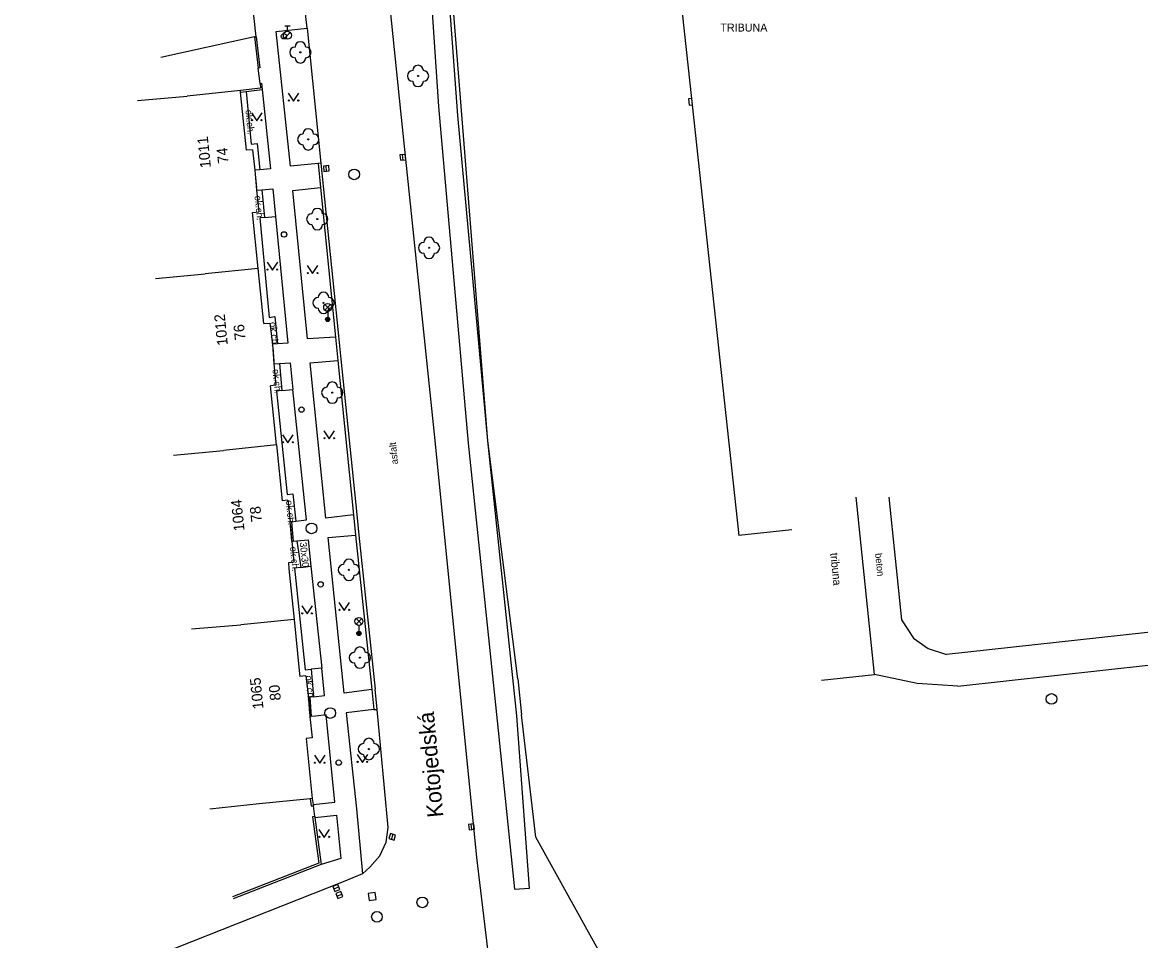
# Model space of a CAD drawing. Extents: x -539694 to -539148, y -1156467 to -1155920.
# Drawn here: x -539664.8 to -539560, y -1156272.3 to -1156186.2 of the extents above; entities that cross this region are included whole.
import ezdxf

# ---------------------------------------------------------------- set-up
doc = ezdxf.new("R2010")
doc.units = 0
for name, color, linetype in [('Vrstva 10', 7, 'Continuous'), ('Vrstva 11', 7, 'Continuous'), ('Vrstva 22', 7, 'Continuous'), ('Vrstva 24', 7, 'Continuous'), ('Vrstva 27', 7, 'Continuous'), ('Vrstva 28', 7, 'Continuous'), ('Vrstva 33', 7, 'Continuous'), ('Vrstva 36', 7, 'Continuous'), ('Vrstva 40', 7, 'Continuous'), ('Vrstva 41', 7, 'Continuous'), ('Vrstva 46', 7, 'Continuous'), ('Vrstva 47', 7, 'Continuous'), ('Vrstva 49', 7, 'Continuous'), ('Vrstva 5', 7, 'Continuous'), ('Vrstva 6', 7, 'Continuous'), ('Vrstva 7', 7, 'Continuous'), ('Vrstva 8', 7, 'Continuous')]:
    doc.layers.add(name, color=color, linetype=linetype)

msp = doc.modelspace()

# ---------------------------------------------------------------- linework, layer by layer
at = {"layer": 'Vrstva 10'}
for p, q in [((-539629.3, -1156194.54), (-539635.12, -1156137.96)), ((-539626.09, -1156225.38), (-539629.3, -1156194.54)), ((-539622.17, -1156264.46), (-539626.09, -1156225.38)), ((-539633.24, -1156234.25), (-539631.72, -1156248.69)), ((-539620.83, -1156275.84), (-539622.17, -1156264.46))]:
    msp.add_line(p, q, dxfattribs=at)
for points in [[(-539630.48, -1156261.66), (-539631.537, -1156250.605), (-539631.72, -1156248.69)], [(-539632.28, -1156268.5), (-539631.61, -1156268.41), (-539631.7, -1156267.74), (-539632.37, -1156267.83), (-539632.28, -1156268.5)]]:
    msp.add_lwpolyline(points, dxfattribs=at)
at = {"layer": 'Vrstva 11'}
for p, q in [((-539627.3, -1156171.99), (-539625.77, -1156194.09)), ((-539623.95, -1156194.94), (-539625.639, -1156171.992)), ((-539640.98, -1156187.07), (-539638.09, -1156186.77)), ((-539638.09, -1156186.77), (-539636.805, -1156199.4)), ((-539639.64, -1156199.69), (-539640.98, -1156187.07)), ((-539642.302, -1156192.518), (-539641.52, -1156199.93)), ((-539625.77, -1156194.09), (-539623.01, -1156225.65)), ((-539636.805, -1156199.4), (-539636.583, -1156201.569)), ((-539637.05, -1156199.44), (-539639.64, -1156199.69)), ((-539639.44, -1156201.98), (-539636.84, -1156201.68)), ((-539638.04, -1156215.87), (-539639.44, -1156201.98)), ((-539636.84, -1156201.68), (-539635.42, -1156215.7)), ((-539636.583, -1156201.569), (-539635.148, -1156215.599)), ((-539642.09, -1156204.5), (-539642.53, -1156204.53)), ((-539642.53, -1156204.53), (-539641.63, -1156213.88)), ((-539641.05, -1156204.42), (-539639.88, -1156216.28)), ((-539635.42, -1156215.7), (-539638.04, -1156215.87)), ((-539635.42, -1156215.7), (-539635.2, -1156217.9)), ((-539635.148, -1156215.599), (-539634.925, -1156217.779)), ((-539637.79, -1156218.13), (-539635.2, -1156217.9)), ((-539636.33, -1156232.68), (-539637.79, -1156218.13)), ((-539635.2, -1156217.9), (-539633.74, -1156232.36)), ((-539634.925, -1156217.779), (-539633.436, -1156232.335)), ((-539640.46, -1156220.71), (-539640.96, -1156220.76)), ((-539640.96, -1156220.76), (-539639.95, -1156230.45)), ((-539638.16, -1156232.83), (-539639.41, -1156220.62)), ((-539623.01, -1156225.65), (-539620.28, -1156251.66)), ((-539584.92, -1156247.33), (-539586.63, -1156230.7)), ((-539583.57, -1156230.69), (-539582.38, -1156242.19)), ((-539633.74, -1156232.36), (-539636.33, -1156232.68)), ((-539633.74, -1156232.36), (-539633.54, -1156234.26)), ((-539633.436, -1156232.335), (-539633.24, -1156234.25)), ((-539639.55, -1156233.02), (-539639.68, -1156233.03)), ((-539639.55, -1156233.02), (-539639.39, -1156234.83)), ((-539639.53, -1156234.84), (-539639.39, -1156234.83)), ((-539636.12, -1156234.49), (-539633.54, -1156234.26)), ((-539634.63, -1156249.08), (-539636.12, -1156234.49)), ((-539633.54, -1156234.26), (-539632.03, -1156248.74)), ((-539638.69, -1156237.28), (-539639.27, -1156237.35)), ((-539639.27, -1156237.35), (-539638.27, -1156246.89)), ((-539637.74, -1156237.16), (-539636.72, -1156246.74)), ((-539509.19, -1156237.87), (-539578.17, -1156245.46)), ((-539582.38, -1156242.19), (-539581.25, -1156243.9)), ((-539581.25, -1156243.9), (-539579.89, -1156244.87)), ((-539579.89, -1156244.87), (-539578.17, -1156245.46)), ((-539577.12, -1156248.42), (-539558.98, -1156246.41)), ((-539638.27, -1156246.89), (-539637.72, -1156246.83)), ((-539589.894, -1156247.841), (-539584.92, -1156247.33)), ((-539580.92, -1156248.17), (-539584.92, -1156247.33)), ((-539577.12, -1156248.42), (-539580.92, -1156248.17)), ((-539637.97, -1156249.46), (-539637.84, -1156249.45)), ((-539637.84, -1156249.45), (-539637.7, -1156251.26)), ((-539632.03, -1156248.74), (-539634.63, -1156249.08)), ((-539631.85, -1156250.61), (-539634.42, -1156250.91)), ((-539637.83, -1156251.27), (-539637.7, -1156251.26)), ((-539635.49, -1156259.29), (-539636.29, -1156251.11)), ((-539634.42, -1156250.91), (-539633.47, -1156259.91)), ((-539620.28, -1156251.66), (-539618.65, -1156267.42)), ((-539617.26, -1156267.35), (-539618.45, -1156251.19)), ((-539637.515, -1156259.509), (-539635.49, -1156259.29)), ((-539633.47, -1156259.91), (-539632.9, -1156266.01)), ((-539632.9, -1156266.01), (-539634.71, -1156266.76)), ((-539634.71, -1156266.76), (-539664.77, -1156278.6)), ((-539618.65, -1156267.42), (-539617.26, -1156267.35))]:
    msp.add_line(p, q, dxfattribs=at)
for points in [[(-539638.09, -1156186.77), (-539638.34, -1156184.59), (-539638.35, -1156184.32)], [(-539643.783, -1156192.694), (-539643.32, -1156197.64), (-539642.77, -1156197.57), (-539642.53, -1156200.02)], [(-539618.45, -1156251.19), (-539621.153, -1156225.416), (-539623.95, -1156194.94)], [(-539636.805, -1156199.4), (-539637.05, -1156199.44), (-539636.84, -1156201.68)], [(-539641.52, -1156199.93), (-539642.53, -1156200.02), (-539643, -1156200.06)], [(-539642.82, -1156201.95), (-539642.34, -1156201.91), (-539642.09, -1156204.5), (-539641.05, -1156204.42)], [(-539642.34, -1156201.91), (-539641.31, -1156201.83), (-539641.05, -1156204.42)], [(-539641.63, -1156213.88), (-539641.1, -1156213.79), (-539640.86, -1156216.34)], [(-539639.88, -1156216.28), (-539640.86, -1156216.34), (-539641.33, -1156216.37)], [(-539641.19, -1156218.22), (-539640.68, -1156218.19), (-539640.46, -1156220.71), (-539639.41, -1156220.62)], [(-539640.68, -1156218.19), (-539639.67, -1156218.12), (-539639.41, -1156220.62)], [(-539639.95, -1156230.45), (-539639.41, -1156230.39), (-539639.15, -1156232.96)], [(-539639.55, -1156233.02), (-539639.15, -1156232.96), (-539638.16, -1156232.83)], [(-539639.39, -1156234.83), (-539639.04, -1156234.79), (-539638.69, -1156237.28), (-539637.74, -1156237.16)], [(-539639.04, -1156234.79), (-539637.99, -1156234.69), (-539637.74, -1156237.16)], [(-539636.72, -1156246.74), (-539637.72, -1156246.83), (-539637.48, -1156249.41), (-539637.84, -1156249.45)], [(-539637.48, -1156249.41), (-539636.46, -1156249.3), (-539636.72, -1156246.74)], [(-539632.03, -1156248.74), (-539631.85, -1156250.61), (-539631.537, -1156250.605)], [(-539636.29, -1156251.11), (-539637.28, -1156251.21), (-539637.7, -1156251.26)], [(-539637.357, -1156260.714), (-539635.34, -1156260.5), (-539634.93, -1156264.57), (-539636.77, -1156265.12)], [(-539632.9, -1156266.01), (-539632.199, -1156265.356), (-539631.277, -1156264.308), (-539630.688, -1156263.041), (-539630.48, -1156261.66)]]:
    msp.add_lwpolyline(points, dxfattribs=at)
at = {"layer": 'Vrstva 22'}
for centre in [(-539638.72, -1156189.03), (-539627.69, -1156191.24), (-539637.98, -1156197.18), (-539637.13, -1156204.65), (-539626.66, -1156207.34), (-539636.55, -1156212.5), (-539635.73, -1156220.91), (-539634.17, -1156237.51), (-539633.14, -1156245.74), (-539632.3, -1156254.3)]:
    msp.add_circle(centre, 0.05, dxfattribs=at)
for centre, start, end in [((-539639.22, -1156189.03), 90, 270), ((-539638.72, -1156188.53), 0, 180), ((-539638.22, -1156189.03), 270, 90), ((-539638.72, -1156189.53), 180, 0), ((-539628.19, -1156191.24), 90, 270), ((-539627.69, -1156190.74), 0, 180), ((-539627.19, -1156191.24), 270, 90), ((-539627.69, -1156191.74), 180, 0), ((-539637.98, -1156196.68), 0, 180), ((-539638.48, -1156197.18), 90, 270), ((-539637.48, -1156197.18), 270, 90), ((-539637.98, -1156197.68), 180, 0), ((-539637.63, -1156204.65), 90, 270), ((-539637.13, -1156204.15), 0, 180), ((-539636.63, -1156204.65), 270, 90), ((-539637.13, -1156205.15), 180, 0), ((-539626.66, -1156206.84), 0, 180), ((-539627.16, -1156207.34), 90, 270), ((-539626.16, -1156207.34), 270, 90), ((-539626.66, -1156207.84), 180, 0), ((-539636.55, -1156212), 0, 180), ((-539637.05, -1156212.5), 90, 270), ((-539636.55, -1156213), 180, 0), ((-539636.05, -1156212.5), 270, 90), ((-539635.73, -1156220.41), 0, 180), ((-539636.23, -1156220.91), 90, 270), ((-539635.73, -1156221.41), 180, 0), ((-539635.23, -1156220.91), 270, 90), ((-539634.67, -1156237.51), 90, 270), ((-539634.17, -1156237.01), 0, 180), ((-539633.67, -1156237.51), 270, 90), ((-539634.17, -1156238.01), 180, 0), ((-539633.64, -1156245.74), 90, 270), ((-539633.14, -1156245.24), 0, 180), ((-539632.64, -1156245.74), 270, 90), ((-539633.14, -1156246.24), 180, 0), ((-539632.8, -1156254.3), 90, 270), ((-539632.3, -1156253.8), 0, 180), ((-539631.8, -1156254.3), 270, 90), ((-539632.3, -1156254.8), 180, 0)]:
    msp.add_arc(centre, 0.5, start, end, dxfattribs=at)
at = {"layer": 'Vrstva 24'}
msp.add_lwpolyline([(-539602.059, -1156193.342), (-539602.357, -1156193.374), (-539602.293, -1156193.97), (-539601.994, -1156193.938)], dxfattribs=at)
at = {"layer": 'Vrstva 27'}
for p, q in [((-539629.096, -1156199.119), (-539629.144, -1156198.621)), ((-539636.266, -1156200.159), (-539636.314, -1156199.661)), ((-539630.184, -1156262.769), (-539630.036, -1156262.291)), ((-539622.656, -1156261.839), (-539622.704, -1156261.341)), ((-539635.592, -1156267.414), (-539635.128, -1156267.226)), ((-539635.292, -1156268.074), (-539634.828, -1156267.886))]:
    msp.add_line(p, q, dxfattribs=at)
for points in [[(-539628.847, -1156199.095), (-539628.895, -1156198.597), (-539629.393, -1156198.645), (-539629.345, -1156199.143)], [(-539636.017, -1156200.135), (-539636.065, -1156199.637), (-539636.563, -1156199.685), (-539636.515, -1156200.183)], [(-539629.945, -1156262.843), (-539629.797, -1156262.365), (-539630.275, -1156262.217), (-539630.423, -1156262.695)], [(-539622.407, -1156261.814), (-539622.456, -1156261.317), (-539622.953, -1156261.366), (-539622.904, -1156261.863)], [(-539635.498, -1156267.646), (-539635.034, -1156267.458), (-539635.222, -1156266.994), (-539635.686, -1156267.182)], [(-539635.198, -1156268.306), (-539634.734, -1156268.118), (-539634.922, -1156267.654), (-539635.386, -1156267.842)]]:
    msp.add_lwpolyline(points, close=True, dxfattribs=at)
for centre in [(-539633.68, -1156200.46), (-539637.67, -1156233.63), (-539568.33, -1156249.61), (-539635.92, -1156250.93), (-539627.29, -1156268.67), (-539631.54, -1156270.02)]:
    msp.add_circle(centre, 0.5, dxfattribs=at)
at = {"layer": 'Vrstva 28'}
for p, q in [((-539640.19, -1156186.554), (-539639.69, -1156186.554)), ((-539639.94, -1156187.054), (-539639.94, -1156186.554)), ((-539640.199, -1156187.701), (-539639.669, -1156187.171))]:
    msp.add_line(p, q, dxfattribs=at)
for centre, radius in [((-539640.26, -1156187.52), 0.25), ((-539639.94, -1156187.43), 0.375), ((-539640.25, -1156206.09), 0.25), ((-539638.61, -1156222.5), 0.25), ((-539636.82, -1156238.88), 0.25), ((-539635.13, -1156255.57), 0.25)]:
    msp.add_circle(centre, radius, dxfattribs=at)
at = {"layer": 'Vrstva 33'}
for p, q in [((-539636.425, -1156213.19), (-539635.895, -1156212.66)), ((-539636.425, -1156212.66), (-539635.895, -1156213.19)), ((-539636.16, -1156213.3), (-539636.16, -1156214.05)), ((-539633.495, -1156242.61), (-539632.965, -1156242.08)), ((-539633.495, -1156242.08), (-539632.965, -1156242.61)), ((-539633.23, -1156242.72), (-539633.23, -1156243.47))]:
    msp.add_line(p, q, dxfattribs=at)
for centre, radius in [((-539636.16, -1156212.925), 0.375), ((-539636.16, -1156214.05), 0.2), ((-539636.16, -1156214.05), 0.145), ((-539636.16, -1156214.05), 0.0876), ((-539633.23, -1156242.345), 0.375), ((-539633.23, -1156243.47), 0.2), ((-539633.23, -1156243.47), 0.145), ((-539633.23, -1156243.47), 0.0876)]:
    msp.add_circle(centre, radius, dxfattribs=at)
at = {"layer": 'Vrstva 36'}
for points in [[(-539639.86, -1156192.84), (-539639.36, -1156193.59), (-539638.86, -1156192.84)], [(-539643.3, -1156194.68), (-539642.8, -1156195.43), (-539642.3, -1156194.68)], [(-539641.84, -1156208.68), (-539641.34, -1156209.43), (-539640.84, -1156208.68)], [(-539638.07, -1156209.01), (-539637.57, -1156209.76), (-539637.07, -1156209.01)], [(-539636.51, -1156224.48), (-539636.01, -1156225.23), (-539635.51, -1156224.48)], [(-539640.38, -1156224.86), (-539639.88, -1156225.61), (-539639.38, -1156224.86)], [(-539638.59, -1156240.89), (-539638.09, -1156241.64), (-539637.59, -1156240.89)], [(-539635.1, -1156240.56), (-539634.6, -1156241.31), (-539634.1, -1156240.56)], [(-539637.41, -1156254.89), (-539636.91, -1156255.64), (-539636.41, -1156254.89)], [(-539633.4, -1156254.8), (-539632.9, -1156255.55), (-539632.4, -1156254.8)], [(-539636.98, -1156261.83), (-539636.48, -1156262.58), (-539635.98, -1156261.83)]]:
    msp.add_lwpolyline(points, dxfattribs=at)
for centre in [(-539639.81, -1156193.54), (-539638.911, -1156193.54), (-539643.25, -1156195.38), (-539642.351, -1156195.38), (-539641.79, -1156209.38), (-539640.891, -1156209.38), (-539638.02, -1156209.71), (-539637.121, -1156209.71), (-539640.33, -1156225.56), (-539639.431, -1156225.56), (-539636.46, -1156225.18), (-539635.561, -1156225.18), (-539635.05, -1156241.26), (-539634.151, -1156241.26), (-539638.54, -1156241.59), (-539637.641, -1156241.59), (-539637.36, -1156255.59), (-539636.461, -1156255.59), (-539633.35, -1156255.5), (-539632.451, -1156255.5), (-539636.93, -1156262.53), (-539636.031, -1156262.53)]:
    msp.add_circle(centre, 0.05, dxfattribs=at)
at = {"layer": 'Vrstva 5'}
for p, q in [((-539606.99, -1156147.74), (-539602.059, -1156193.342)), ((-539653.986, -1156193.541), (-539649.314, -1156193.118)), ((-539644.34, -1156192.61), (-539649.314, -1156193.118)), ((-539602.059, -1156193.342), (-539601.994, -1156193.938)), ((-539601.994, -1156193.938), (-539597.63, -1156234.3)), ((-539643.21, -1156198.15), (-539643.775, -1156198.207)), ((-539643.21, -1156198.15), (-539643, -1156200.06)), ((-539643, -1156200.06), (-539642.82, -1156201.95)), ((-539642.82, -1156201.95), (-539642.61, -1156203.96)), ((-539643.19, -1156204.018), (-539642.61, -1156203.96)), ((-539642.66, -1156209.27), (-539643.19, -1156204.018)), ((-539652.3, -1156210.212), (-539647.634, -1156209.778)), ((-539642.66, -1156209.27), (-539647.634, -1156209.778)), ((-539642.128, -1156214.446), (-539642.66, -1156209.27)), ((-539642.128, -1156214.446), (-539641.58, -1156214.39)), ((-539641.58, -1156214.39), (-539641.33, -1156216.37)), ((-539641.33, -1156216.37), (-539641.19, -1156218.22)), ((-539641.19, -1156218.22), (-539641.01, -1156220.21)), ((-539641.01, -1156220.21), (-539641.53, -1156220.263)), ((-539640.96, -1156225.81), (-539641.53, -1156220.263)), ((-539650.597, -1156226.779), (-539645.934, -1156226.318)), ((-539640.96, -1156225.81), (-539645.934, -1156226.318)), ((-539640.96, -1156225.81), (-539640.432, -1156231.044)), ((-539639.9, -1156230.99), (-539640.432, -1156231.044)), ((-539639.9, -1156230.99), (-539639.68, -1156233.03)), ((-539639.53, -1156234.84), (-539639.68, -1156233.03)), ((-539592.659, -1156233.762), (-539597.63, -1156234.3)), ((-539639.53, -1156234.84), (-539639.32, -1156236.8)), ((-539639.32, -1156236.8), (-539639.846, -1156236.853)), ((-539639.31, -1156242.17), (-539644.284, -1156242.678)), ((-539648.908, -1156243.032), (-539644.284, -1156242.678)), ((-539638.21, -1156247.45), (-539638.765, -1156247.507)), ((-539638.21, -1156247.45), (-539637.97, -1156249.46)), ((-539637.97, -1156249.46), (-539637.83, -1156251.27)), ((-539637.83, -1156251.27), (-539637.62, -1156253.25)), ((-539637.62, -1156253.25), (-539638.174, -1156253.306)), ((-539638.174, -1156253.306), (-539637.6, -1156258.93)), ((-539642.574, -1156259.438), (-539647.217, -1156259.93))]:
    msp.add_line(p, q, dxfattribs=at)
for points in [[(-539643.775, -1156198.207), (-539644.322, -1156192.758), (-539644.34, -1156192.61)], [(-539639.846, -1156236.853), (-539639.79, -1156237.404), (-539639.31, -1156242.17)], [(-539639.31, -1156242.17), (-539638.823, -1156246.938), (-539638.765, -1156247.507)], [(-539637.6, -1156258.93), (-539637.797, -1156258.959), (-539642.574, -1156259.438)]]:
    msp.add_lwpolyline(points, dxfattribs=at)
at = {"layer": 'Vrstva 6'}
for p, q in [((-539642.96, -1156200.43), (-539642.84, -1156201.7)), ((-539641.31, -1156216.65), (-539641.21, -1156217.95)), ((-539639.67, -1156233.2), (-539639.55, -1156234.57)), ((-539637.95, -1156249.66), (-539637.85, -1156250.96))]:
    msp.add_line(p, q, dxfattribs=at)
at = {"layer": 'Vrstva 7'}
for p, q in [((-539621.153, -1156225.416), (-539626.515, -1156158.135)), ((-539643.009, -1156187.586), (-539651.8, -1156189.512)), ((-539643.009, -1156187.586), (-539642.86, -1156187.57)), ((-539643.009, -1156187.586), (-539642.679, -1156190.506)), ((-539642.86, -1156187.57), (-539642.53, -1156190.49)), ((-539642.53, -1156190.49), (-539642.679, -1156190.506)), ((-539642.499, -1156191.942), (-539642.35, -1156191.93)), ((-539642.499, -1156191.942), (-539642.463, -1156192.387)), ((-539642.35, -1156191.93), (-539642.302, -1156192.518)), ((-539642.463, -1156192.387), (-539644.34, -1156192.61)), ((-539618.35, -1156247.74), (-539621.153, -1156225.416)), ((-539616.66, -1156262.57), (-539618.01, -1156251.11)), ((-539637.797, -1156258.959), (-539637.697, -1156259.639)), ((-539637.697, -1156259.639), (-539637.5, -1156259.61)), ((-539637.37, -1156260.62), (-539637.568, -1156260.646)), ((-539637.568, -1156260.646), (-539636.989, -1156264.991)), ((-539602.201, -1156288.522), (-539616.66, -1156262.57)), ((-539636.989, -1156264.991), (-539645.093, -1156268.164)), ((-539636.77, -1156265.12), (-539645.02, -1156268.35))]:
    msp.add_line(p, q, dxfattribs=at)
for points in [[(-539644.322, -1156192.758), (-539643.783, -1156192.694), (-539642.302, -1156192.518)], [(-539637.6, -1156258.93), (-539637.515, -1156259.509), (-539637.5, -1156259.61)], [(-539637.37, -1156260.62), (-539637.357, -1156260.714), (-539636.77, -1156265.12)]]:
    msp.add_lwpolyline(points, dxfattribs=at)
at = {"layer": 'Vrstva 8'}
for p, q in [((-539642.86, -1156187.57), (-539643.23, -1156184.15)), ((-539642.499, -1156191.942), (-539642.679, -1156190.506)), ((-539618.35, -1156247.74), (-539618.01, -1156251.11)), ((-539637.37, -1156260.62), (-539637.5, -1156259.61))]:
    msp.add_line(p, q, dxfattribs=at)

# ---------------------------------------------------------------- texts
at = {"layer": 'Vrstva 40'}
for s, rotation, p in [('ok.ch.', 275.35221, (-539643.87, -1156194.44)), ('ok.ch.', 275.35221, (-539643.01, -1156202.48)), ('ok.ch.', 275.35221, (-539641.6, -1156214.32)), ('ok.ch.', 275.35221, (-539641.33, -1156218.73)), ('asfalt', 95.76243, (-539629.561, -1156227.599)), ('ok.ch.', 275.35221, (-539640.08, -1156231.03)), ('30x30', 275.86755, (-539638.78, -1156234.95)), ('ok.ch.', 275.35221, (-539639.7, -1156235.37)), ('beton', 275.90784, (-539584.866, -1156235.978)), ('ok.ch.', 275.31459, (-539638.24, -1156247.44))]:
    msp.add_text(s, height=0.65, rotation=rotation, dxfattribs=at).set_placement(p)
at = {"layer": 'Vrstva 41'}
msp.add_text('TRIBUNA', height=0.75, dxfattribs=at).set_placement((-539599.359, -1156187.082))
msp.add_text('tribuna', height=0.75, rotation=275.87088, dxfattribs=at).set_placement((-539589.073, -1156235.956))
at = {"layer": 'Vrstva 46'}
for s, p in [('74', (-539645.432, -1156199.395)), ('76', (-539643.856, -1156215.938)), ('78', (-539642.322, -1156232.992)), ('80', (-539640.541, -1156249.717))]:
    msp.add_text(s, height=1, rotation=95.76243, dxfattribs=at).set_placement(p)
at = {"layer": 'Vrstva 47'}
for s, p in [('1011', (-539647.097, -1156199.82)), ('1012', (-539645.513, -1156216.453)), ('1064', (-539643.944, -1156233.844)), ('1065', (-539642.167, -1156250.526))]:
    msp.add_text(s, height=1, rotation=95.76243, dxfattribs=at).set_placement(p)
at = {"layer": 'Vrstva 49'}
msp.add_text('Kotojedská', height=1.5, rotation=95.18138, dxfattribs=at).set_placement((-539625.315, -1156260.644))

doc.saveas('drawing.dxf')
